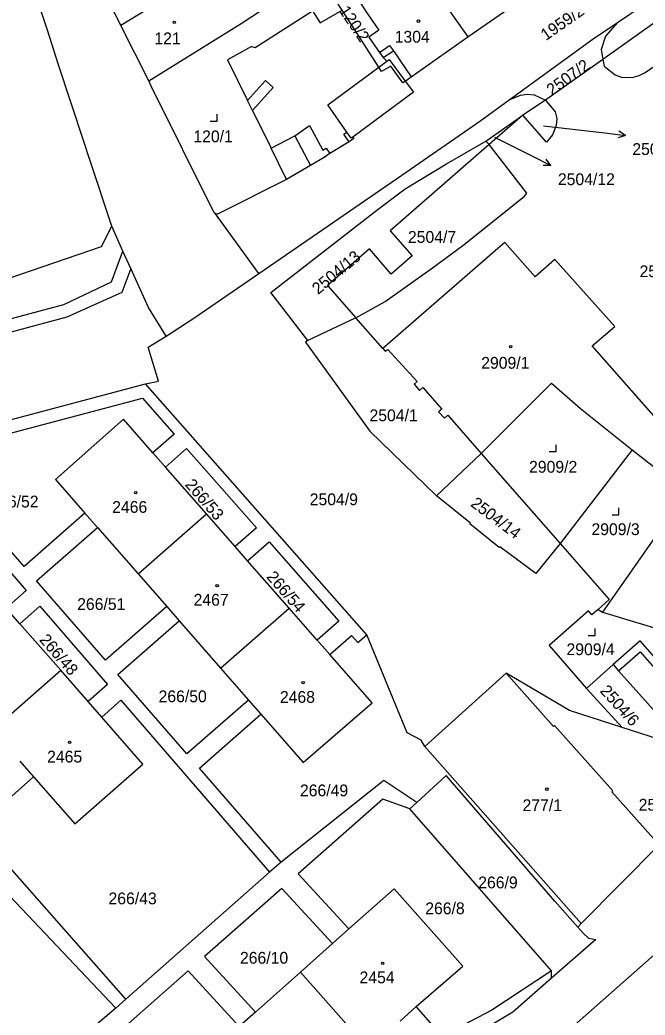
# Model space of a CAD drawing. Extents: x -679220 to -673243, y -1075091 to -1066557.
# Drawn here: x -676311.1 to -676221, y -1072010.2 to -1071866.6 of the extents above; entities that cross this region are included whole.
import ezdxf

# ---------------------------------------------------------------- set-up
doc = ezdxf.new("R2010")
doc.units = 0
for name, color, linetype in [('Hranice parcel', 7, 'Continuous'), ('Parcelní čísla', 7, 'Continuous'), ('Pop  PČ popisy', 7, 'Continuous'), ('Vnitřní kresba', 7, 'Continuous'), ('Značky budov', 7, 'Continuous'), ('Značky kultur', 7, 'Continuous')]:
    doc.layers.add(name, color=color, linetype=linetype)

msp = doc.modelspace()

# ---------------------------------------------------------------- linework, layer by layer
at = {"layer": 'Hranice parcel'}
for p, q in [((-676296.55, -1071867.44), (-676300.63, -1071859.07)), ((-676292.52, -1071875.45), (-676296.55, -1071867.44)), ((-676227.08, -1071872.34), (-676235.34, -1071878.23)), ((-676235.34, -1071878.23), (-676238.59, -1071880.39)), ((-676243.91, -1071884.12), (-676238.59, -1071880.39)), ((-676238.59, -1071880.39), (-676243.45, -1071884.63)), ((-676243.91, -1071884.12), (-676243.45, -1071884.63)), ((-676276.66, -1071903.24), (-676282.91, -1071894.61)), ((-676296.28, -1071899.99), (-676297.85, -1071896.38)), ((-676295.13, -1071902.52), (-676296.28, -1071899.99)), ((-676262.69, -1071909.6), (-676269.62, -1071912.9)), ((-676258.77, -1071914.06), (-676262.69, -1071909.6)), ((-676261.1, -1071955.35), (-676292.99, -1071919.16)), ((-676290.15, -1071931.15), (-676291.95, -1071929.1)), ((-676251.05, -1071935.29), (-676244.6, -1071929.19)), ((-676244.6, -1071929.19), (-676233.19, -1071942.19)), ((-676222.83, -1071928.67), (-676233.19, -1071942.19)), ((-676284.24, -1071937.88), (-676290.15, -1071931.15)), ((-676301.74, -1071937.8), (-676299.95, -1071939.84)), ((-676294.07, -1071946.56), (-676284.24, -1071937.88)), ((-676280.1, -1071942.61), (-676284.24, -1071937.88)), ((-676299.95, -1071939.84), (-676294.07, -1071946.56)), ((-676278.3, -1071944.66), (-676280.1, -1071942.61)), ((-676272.29, -1071951.51), (-676278.3, -1071944.66)), ((-676294.07, -1071946.56), (-676289.95, -1071951.28)), ((-676311.12, -1071953.74), (-676313.09, -1071951.49)), ((-676289.95, -1071951.28), (-676288.16, -1071953.33)), ((-676282.18, -1071960.17), (-676272.29, -1071951.51)), ((-676268.24, -1071956.12), (-676272.29, -1071951.51)), ((-676227.73, -1071951.67), (-676227.09, -1071952.06)), ((-676227.09, -1071952.06), (-676212.87, -1071956.4)), ((-676305.24, -1071960.46), (-676311.12, -1071953.74)), ((-676288.16, -1071953.33), (-676282.18, -1071960.17)), ((-676266.45, -1071958.17), (-676268.24, -1071956.12)), ((-676315.07, -1071969.09), (-676305.24, -1071960.46)), ((-676301.3, -1071964.97), (-676305.24, -1071960.46)), ((-676282.18, -1071960.17), (-676278.15, -1071964.77)), ((-676241.02, -1071960.86), (-676252.73, -1071971.48)), ((-676224.78, -1071960.53), (-676214.75, -1071971.79)), ((-676229.4, -1071963.07), (-676224.25, -1071968.72)), ((-676299.33, -1071967.22), (-676301.3, -1071964.97)), ((-676278.15, -1071964.77), (-676276.37, -1071966.81)), ((-676214.75, -1071971.79), (-676224.25, -1071968.72)), ((-676252.73, -1071971.48), (-676230.19, -1071997.01)), ((-676311.13, -1071973.59), (-676309.16, -1071975.83)), ((-676253.86, -1071979.52), (-676254.89, -1071980.47)), ((-676234.44, -1072003.82), (-676254.89, -1071980.47)), ((-676218.96, -1071985.64), (-676230.19, -1071997.01)), ((-676273.47, -1071988.14), (-676275.14, -1071989.58)), ((-676275.14, -1071989.58), (-676295.84, -1072007.9)), ((-676230.19, -1071997.01), (-676230.67, -1071997.5)), ((-676263.67, -1071997.76), (-676266.03, -1071999.86)), ((-676266.03, -1071999.86), (-676270.68, -1072004)), ((-676270.68, -1072004), (-676277.17, -1072009.77)), ((-676260.82, -1072015.12), (-676270.68, -1072004)), ((-676234.47, -1072004.88), (-676234.44, -1072003.82)), ((-676295.84, -1072007.9), (-676297.3, -1072009.2)), ((-676297.3, -1072009.2), (-676324.68, -1072032.42)), ((-676277.17, -1072009.77), (-676279.52, -1072011.86)), ((-676253.97, -1072008.98), (-676256.31, -1072011.08))]:
    msp.add_line(p, q, dxfattribs=at)
for points in [[(-676272.54, -1071852.2), (-676278.73, -1071855.99), (-676281.35, -1071857.71), (-676284.52, -1071859.78), (-676284.4, -1071860.03), (-676286.52, -1071861.31), (-676296.55, -1071867.44)], [(-676257.86, -1071852.9), (-676252.84, -1071860.14), (-676246.51, -1071869.08)], [(-676297.85, -1071896.38), (-676301.01, -1071886.96), (-676301.89, -1071884.16), (-676305.6, -1071872.98), (-676307.16, -1071868.11), (-676312.04, -1071853.49)], [(-676264.75, -1071857.63), (-676261.43, -1071863.25), (-676262.28, -1071863.78), (-676261, -1071865.74), (-676259.36, -1071868.1), (-676260.81, -1071869.11), (-676259.26, -1071871.34), (-676258.75, -1071872.08), (-676258.23, -1071872.61), (-676257.87, -1071872.34), (-676255.55, -1071875.46)], [(-676206.65, -1071856.66), (-676214.57, -1071863.42), (-676227.08, -1071872.34)], [(-676224.96, -1071866.99), (-676210.13, -1071856.97), (-676206.65, -1071856.66)], [(-676246.51, -1071869.08), (-676234.23, -1071860.52), (-676231.96, -1071858.9)], [(-676292.52, -1071875.45), (-676279.21, -1071867.15), (-676268.14, -1071859.83)], [(-676255.55, -1071875.46), (-676255.88, -1071875.71), (-676257.62, -1071873.29), (-676258.97, -1071874.1), (-676259.38, -1071873.46), (-676264.66, -1071865.25), (-676268.14, -1071859.83)], [(-676240.59, -1071878.19), (-676228.46, -1071869.36), (-676224.96, -1071866.99)], [(-676224.96, -1071866.99), (-676226.67, -1071868.98), (-676227.28, -1071870.89), (-676227.08, -1071872.34)], [(-676255.55, -1071875.46), (-676254.68, -1071874.85), (-676246.51, -1071869.08)], [(-676227.08, -1071872.34), (-676226.86, -1071873.32), (-676225.29, -1071874.56), (-676224.35, -1071874.89), (-676222.83, -1071874.93), (-676221.84, -1071874.67), (-676220.94, -1071874.24), (-676216.81, -1071871.39), (-676205.41, -1071888.05), (-676204.87, -1071888.91), (-676204.42, -1071889.82), (-676203.93, -1071891.77), (-676201.63, -1071906.65), (-676192.52, -1071929.9), (-676184.66, -1071947.23), (-676184.22, -1071948.69), (-676184.11, -1071949.73), (-676184.14, -1071951.2), (-676184.39, -1071952.29)], [(-676282.91, -1071894.61), (-676283.12, -1071894.47), (-676292.18, -1071876.22), (-676292.52, -1071875.45)], [(-676255.55, -1071875.46), (-676254.38, -1071877.04), (-676263.13, -1071883.55), (-676262.98, -1071883.75), (-676263.62, -1071884.22), (-676266.43, -1071885.93), (-676267.27, -1071886.47), (-676269.23, -1071887.62), (-676272.7, -1071889.66), (-676282.63, -1071894.68), (-676282.91, -1071894.61)], [(-676240.59, -1071878.19), (-676238.95, -1071877.52), (-676237.96, -1071877.35), (-676236.96, -1071877.45), (-676235.34, -1071878.23)], [(-676276.66, -1071903.24), (-676256.03, -1071889.05), (-676244.66, -1071881.14), (-676240.59, -1071878.19)], [(-676235.34, -1071878.23), (-676233.92, -1071879.9), (-676233.69, -1071880.86), (-676233.78, -1071881.85), (-676234.34, -1071883.21), (-676235.2, -1071884.26), (-676238.59, -1071880.39)], [(-676269.62, -1071912.9), (-676274.94, -1071905.98), (-676259.64, -1071894.1), (-676255.56, -1071890.99), (-676249.59, -1071887.42), (-676243.91, -1071884.12)], [(-676243.45, -1071884.63), (-676257.71, -1071897.06), (-676254.54, -1071900.66), (-676257.57, -1071903.31), (-676260.73, -1071899.68), (-676266.77, -1071904.94), (-676262.69, -1071909.6)], [(-676262.69, -1071909.6), (-676258.47, -1071907.24), (-676251.61, -1071902.41), (-676247.23, -1071899.18), (-676238.4, -1071892.1), (-676238.04, -1071891.65), (-676243.45, -1071884.63)], [(-676386.32, -1071921.67), (-676373.19, -1071918.89), (-676362.98, -1071916.66), (-676353.15, -1071914.69), (-676349.6, -1071914.02), (-676331.48, -1071909.81), (-676326.61, -1071908.65), (-676299.34, -1071899.31), (-676297.85, -1071896.38)], [(-676212.87, -1071956.4), (-676201.2, -1071946.34), (-676200.07, -1071945.3), (-676206.47, -1071938.1), (-676204.7, -1071936.5), (-676205.81, -1071935.25), (-676207.9, -1071937.16), (-676228.58, -1071913.66), (-676225.33, -1071910.89), (-676233.96, -1071901.19), (-676236.8, -1071903.68), (-676241.2, -1071898.74), (-676242.19, -1071899.63), (-676258.77, -1071914.06)], [(-676387.58, -1071941.35), (-676384.43, -1071936.96), (-676375.96, -1071928.98), (-676364.91, -1071923.77), (-676304.78, -1071907.71), (-676297.93, -1071904.43), (-676296.28, -1071899.99)], [(-676295.13, -1071902.52), (-676296.41, -1071905.95), (-676304.35, -1071909.5), (-676364.66, -1071925.74), (-676375.64, -1071931.09), (-676382.94, -1071938.2), (-676387.67, -1071944.57), (-676393.17, -1071962.19), (-676409.55, -1072024.04), (-676425.12, -1072082.52), (-676427.14, -1072091.8), (-676426.89, -1072108.9), (-676422.15, -1072126.21), (-676412.96, -1072141.55), (-676403.18, -1072152.89), (-676393.86, -1072163.85), (-676389.15, -1072169.1)], [(-676290.05, -1071912.25), (-676292.6, -1071908.13), (-676295.13, -1071902.52)], [(-676290.05, -1071912.25), (-676286.02, -1071909.68), (-676276.66, -1071903.24)], [(-676292.99, -1071919.16), (-676291.15, -1071918.74), (-676292.61, -1071913.87), (-676290.05, -1071912.25)], [(-676269.62, -1071912.9), (-676269.95, -1071913.15), (-676260.68, -1071925.96), (-676251.05, -1071935.29)], [(-676258.77, -1071914.06), (-676258.43, -1071914.45), (-676258.05, -1071914.18), (-676253.84, -1071918.81), (-676254.27, -1071919.19), (-676253.48, -1071920.09), (-676253, -1071919.67), (-676250.29, -1071922.77), (-676250.74, -1071923.16), (-676249.91, -1071924.1), (-676249.43, -1071923.68), (-676244.6, -1071929.19)], [(-676381.82, -1071949.81), (-676378.12, -1071943.23), (-676365.91, -1071938.49), (-676327.4, -1071928.26), (-676292.99, -1071919.16)], [(-676244.6, -1071929.19), (-676234.45, -1071919.06), (-676230.27, -1071922.71), (-676222.83, -1071928.67)], [(-676301.74, -1071937.8), (-676310.53, -1071945.49), (-676324.5, -1071929.42), (-676293.47, -1071921.21), (-676288.89, -1071926.41), (-676291.95, -1071929.1)], [(-676291.95, -1071929.1), (-676296.21, -1071924.24), (-676305.98, -1071932.95), (-676301.74, -1071937.8)], [(-676290.15, -1071931.15), (-676287.09, -1071928.46), (-676277.01, -1071939.9), (-676280.1, -1071942.61)], [(-676222.83, -1071928.67), (-676214.99, -1071934.79), (-676227.09, -1071952.06)], [(-676233.19, -1071942.19), (-676236.74, -1071946.52), (-676241.9, -1071942.64), (-676241.99, -1071942.76), (-676246.23, -1071939.35), (-676246.13, -1071939.22), (-676251.05, -1071935.29)], [(-676322.91, -1071940.27), (-676319.95, -1071937.68), (-676310.2, -1071948.96), (-676313.09, -1071951.49)], [(-676289.95, -1071951.28), (-676298.78, -1071959.01), (-676308.75, -1071947.54), (-676299.95, -1071939.84)], [(-676278.3, -1071944.66), (-676275.2, -1071941.94), (-676265.12, -1071953.38), (-676268.24, -1071956.12)], [(-676233.19, -1071942.19), (-676226.13, -1071950.24), (-676227.73, -1071951.67)], [(-676311.12, -1071953.74), (-676308.25, -1071951.23), (-676298.5, -1071962.52), (-676301.3, -1071964.97)], [(-676227.73, -1071951.67), (-676228.63, -1071952.47), (-676229.14, -1071951.9), (-676234.8, -1071956.91), (-676229.4, -1071963.07)], [(-676278.15, -1071964.77), (-676287.04, -1071972.53), (-676297, -1071961.06), (-676288.16, -1071953.33)], [(-676266.45, -1071958.17), (-676263.32, -1071955.43), (-676262.41, -1071956.46), (-676261.1, -1071955.35)], [(-676252.73, -1071971.48), (-676253.26, -1071970.55), (-676255.28, -1071969.49), (-676261.1, -1071955.35)], [(-676224.78, -1071960.53), (-676221.69, -1071957.8), (-676218.56, -1071961.34), (-676217.78, -1071960.65), (-676212.87, -1071956.4)], [(-676276.37, -1071966.81), (-676270.27, -1071973.78), (-676260.32, -1071965.15), (-676266.45, -1071958.17)], [(-676229.4, -1071963.07), (-676225.56, -1071959.65), (-676224.78, -1071960.53)], [(-676218.96, -1071985.64), (-676225.76, -1071978), (-676225.61, -1071977.87), (-676234.03, -1071968.41), (-676234.18, -1071968.55), (-676241.02, -1071960.86)], [(-676224.25, -1071968.72), (-676231.89, -1071966.26), (-676241.02, -1071960.86)], [(-676299.33, -1071967.22), (-676296.55, -1071964.78), (-676275.14, -1071989.58)], [(-676273.47, -1071988.14), (-676285.25, -1071974.58), (-676276.37, -1071966.81)], [(-676309.16, -1071975.83), (-676303.21, -1071982.62), (-676293.39, -1071974.01), (-676299.33, -1071967.22)], [(-676295.84, -1072007.9), (-676317.6, -1071983.28), (-676309.16, -1071975.83)], [(-676253.86, -1071979.52), (-676258.66, -1071976.34), (-676273.47, -1071988.14)], [(-676230.67, -1071997.5), (-676234, -1071993.76), (-676249.65, -1071975.66), (-676253.86, -1071979.52)], [(-676254.89, -1071980.47), (-676258.79, -1071979.07), (-676271, -1071989.84), (-676263.67, -1071997.76)], [(-676259.54, -1072039.89), (-676259.93, -1072037.81), (-676259.05, -1072036.28), (-676207.78, -1071991.04)], [(-676297.3, -1072009.2), (-676313.46, -1071992.13), (-676315.85, -1071994.26)], [(-676266.03, -1071999.86), (-676273.36, -1071991.92), (-676284.49, -1072001.73), (-676277.17, -1072009.77)], [(-676253.97, -1072008.98), (-676247.27, -1072003.13), (-676257.17, -1071991.98), (-676263.67, -1071997.76)], [(-676230.67, -1071997.5), (-676229.92, -1071998.37), (-676229.11, -1071999.1), (-676228.07, -1071999.29), (-676234.47, -1072004.88)], [(-676279.52, -1072011.86), (-676286.84, -1072003.8), (-676297.97, -1072013.61), (-676290.66, -1072021.77)], [(-676234.44, -1072003.82), (-676243.07, -1072009.5), (-676250.25, -1072013.23), (-676253.97, -1072008.98)], [(-676234.47, -1072004.88), (-676240.04, -1072009.78), (-676249.88, -1072015.68), (-676262.29, -1072027.06), (-676264.12, -1072028.98), (-676275.42, -1072039.24), (-676288.64, -1072051.8), (-676300.61, -1072065.52), (-676311.55, -1072079.68), (-676327.13, -1072100.25), (-676343.64, -1072125.3), (-676355.54, -1072152.07)]]:
    msp.add_lwpolyline(points, dxfattribs=at)
at = {"layer": 'Pop  PČ popisy'}
for p, q in [((-676235.63, -1071881.91), (-676226.79, -1071882.93)), ((-676242.66, -1071883.57), (-676237.22, -1071886.28)), ((-676226.79, -1071882.93), (-676223.81, -1071883.3)), ((-676223.81, -1071883.3), (-676224.87, -1071883.67)), ((-676223.81, -1071883.3), (-676224.74, -1071882.68)), ((-676237.22, -1071886.28), (-676234.55, -1071887.64)), ((-676234.55, -1071887.64), (-676235.67, -1071887.63)), ((-676234.55, -1071887.64), (-676235.21, -1071886.74))]:
    msp.add_line(p, q, dxfattribs=at)
at = {"layer": 'Vnitřní kresba'}
for p, q in [((-676277.18, -1071870.6), (-676268.92, -1071865.35)), ((-676268.92, -1071865.35), (-676267.84, -1071867.05)), ((-676267.84, -1071867.05), (-676264.66, -1071865.25)), ((-676277.75, -1071870.47), (-676281.17, -1071872.41)), ((-676277.75, -1071870.47), (-676277.18, -1071870.6)), ((-676259.26, -1071871.34), (-676257.81, -1071870.34)), ((-676257.81, -1071870.34), (-676257.27, -1071871.11)), ((-676258.75, -1071872.08), (-676257.27, -1071871.11)), ((-676257.27, -1071871.11), (-676254.68, -1071874.85)), ((-676281.17, -1071872.41), (-676278.29, -1071878.26)), ((-676266.73, -1071878.91), (-676259.38, -1071873.46)), ((-676259.38, -1071873.46), (-676258.23, -1071872.61)), ((-676278.29, -1071878.26), (-676275.73, -1071875.39)), ((-676274.58, -1071876.37), (-676277.57, -1071879.73)), ((-676275.73, -1071875.39), (-676274.58, -1071876.37)), ((-676277.57, -1071879.73), (-676278.29, -1071878.26)), ((-676263.97, -1071882.83), (-676266.73, -1071878.91)), ((-676277.57, -1071879.73), (-676274.9, -1071885.16)), ((-676271.48, -1071883.35), (-676269.38, -1071881.89)), ((-676269.38, -1071881.89), (-676267.42, -1071885.42)), ((-676274.9, -1071885.16), (-676271.48, -1071883.35)), ((-676271.48, -1071883.35), (-676269.23, -1071887.62)), ((-676264.39, -1071883.13), (-676263.97, -1071882.83)), ((-676263.62, -1071884.22), (-676264.39, -1071883.13)), ((-676263.33, -1071883.7), (-676263.97, -1071882.83)), ((-676263.13, -1071883.55), (-676263.33, -1071883.7)), ((-676272.7, -1071889.66), (-676274.9, -1071885.16)), ((-676267.42, -1071885.42), (-676266.94, -1071885.12)), ((-676266.94, -1071885.12), (-676266.43, -1071885.93)), ((-676221.69, -1071956.23), (-676225.56, -1071959.65)), ((-676217.78, -1071960.65), (-676221.69, -1071956.23))]:
    msp.add_line(p, q, dxfattribs=at)
at = {"layer": 'Značky budov'}
for centre in [(-676288.86, -1071866.99), (-676253.65, -1071866.82), (-676240.36, -1071913.78), (-676294.42, -1071934.84), (-676282.68, -1071948.25), (-676270.28, -1071962.26), (-676303.95, -1071970.85), (-676235.13, -1071977.61), (-676258.8, -1072002.75)]:
    msp.add_circle(centre, 0.175, dxfattribs=at)
at = {"layer": 'Značky kultur'}
for p, q in [((-676282.67, -1071881.25), (-676282.67, -1071880.25)), ((-676283.67, -1071881.25), (-676282.67, -1071881.25)), ((-676233.79, -1071928.92), (-676233.79, -1071927.92)), ((-676234.79, -1071928.92), (-676233.79, -1071928.92)), ((-676225.73, -1071938.05), (-676224.73, -1071938.05)), ((-676224.73, -1071938.05), (-676224.73, -1071937.05)), ((-676228.16, -1071955.44), (-676228.16, -1071954.44)), ((-676229.16, -1071955.44), (-676228.16, -1071955.44))]:
    msp.add_line(p, q, dxfattribs=at)

# ---------------------------------------------------------------- texts
at = {"layer": 'Parcelní čísla'}
for s, rotation, p in [('120/2', 304, (-676265.19, -1071865.29)), ('1959/2', 35, (-676235.27, -1071869.7)), ('2507/2', 36, (-676234.41, -1071877.64)), ('2504/13', 40, (-676268.12, -1071906.34)), ('266/53', 311, (-676287.4, -1071933.73)), ('2504/14', 323, (-676246.26, -1071936.68)), ('266/54', 311, (-676275.66, -1071947.04)), ('266/48', 311, (-676308.42, -1071956.12)), ('2504/6', 312, (-676227.57, -1071963.51))]:
    msp.add_text(s, height=1.7, rotation=rotation, dxfattribs=at).set_placement(p)
for s, p in [('121', (-676291.73, -1071870.15)), ('1304', (-676257.08, -1071869.92)), ('120/1', (-676286.11, -1071884.29)), ('2504/8', (-676222.81, -1071886.12)), ('2504/12', (-676233.54, -1071890.47)), ('2504/7', (-676255.17, -1071898.8)), ('2507/1', (-676221.76, -1071903.75)), ('2909/1', (-676244.6, -1071916.96)), ('2504/1', (-676260.71, -1071924.53)), ('2909/2', (-676237.7, -1071931.96)), ('266/52', (-676315.39, -1071936.97)), ('2504/9', (-676269.33, -1071936.65)), ('2466', (-676297.82, -1071937.75)), ('2909/3', (-676228.7, -1071940.96)), ('2467', (-676286.08, -1071951.14)), ('266/51', (-676302.87, -1071951.76)), ('2909/4', (-676232.3, -1071958.28)), ('266/50', (-676291.13, -1071965.07)), ('2468', (-676273.63, -1071965.16)), ('2465', (-676307.2, -1071973.77)), ('266/49', (-676270.74, -1071978.64)), ('277/1', (-676238.64, -1071980.78)), ('2504/2', (-676221.89, -1071980.71)), ('266/9', (-676245.03, -1071991.92)), ('266/43', (-676298.35, -1071994.22)), ('266/8', (-676252.67, -1071995.65)), ('266/10', (-676279.39, -1072002.79)), ('2454', (-676262.15, -1072005.61))]:
    msp.add_text(s, height=1.7, dxfattribs=at).set_placement(p)

doc.saveas('drawing.dxf')
